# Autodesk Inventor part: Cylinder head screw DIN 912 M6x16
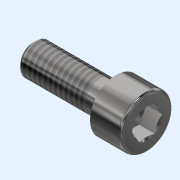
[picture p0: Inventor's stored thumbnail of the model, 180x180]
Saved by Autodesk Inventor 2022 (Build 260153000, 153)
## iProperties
Part Number: Cylinder head screw DIN 912 M6x16
Material: Generico
Catalog Web Link: www.cadenas.de
Description: DIN 912-Cylinder head screws cap screws
Vendor: METALWORK
Document SubType Name: Modeling
Designer: partserver
Manufacturer: METALWORK
Mass: 0.844568 g
Surface Area: 6.8049 cm^2
Volume: 0.844568 cm^3
Density: 1 g/cm^3
Appearance: Acciaio - Lucido
Category: PARTsolutions
Company: METALWORK
PSOL_IDENT_0: {$CADENAS_DATA\23d-libs\metalwork\commonpool\din_912.prj},208 {VTYP=3D},{NB=Cylinder head screw DIN
PSOL_IDENT_1: 912 M6x16},{LINA=Cylinder head screw DIN 912 M6x16},{NN=DIN 912},{DATE=09.11.2020 15:05:54},{GEOMDAT
PSOL_IDENT_2: E=27.11.2019 13:03:54},{VERSION=},{LINEID=690},{WBVAR=},{WBNUMERIC=}  {NB=Zylinderschraube DIN 912 M
PSOL_IDENT_3: 6x16},{LINA=Zylinderschraube DIN 912 M6x16},{KT=X},{IDNR=},{VER=x},{GEW=0},{D=6.000},{D3=4.773},{P=1
PSOL_IDENT_4: .000},{L=16.000},{B=13},{BX=24.000},{LS=0},{LG=3},{DK=10.000},{DA=6.800},{DS=6.000},{E=5.720},{F=0.6
PSOL_IDENT_5: 80},{K=6.000},{R=0.250},{S=5.000},{T=3.000},{V=0.600},{DW=9.380},{W=2.300},{NENN=M6x16}
NB: Cylinder head screw DIN 912 M6x16
NN: DIN 912
NT: Cylinder head screws cap screws
NBSYN: Cylinder head screw DIN 912 $NENN.
LINA: Cylinder head screw DIN 912 M6x16
CATALOG: Metalwork
VER: x
GEW: 0
D: 6
D3: 4.773
P: 1
L: 16
BX: 24
DK: 10
DA: 6.8
DS: 6
E: 5.72
F: 0.68
K: 6
R: 0.25
S: 5
T: 3
V: 0.6
DW: 9.38
W: 2.3
SUPPLIER: METALWORK
ARTICLENO: Cylinder head screw DIN 912 M6x16
BOMINFO: Cylinder head screw DIN 912 M6x16
CREATOR: CADENAS GmbH
Title: Cylinder head screw DIN 912 M6x16
Author: Cadenas PARTsolutions
Comments: Cylinder head screws cap screws
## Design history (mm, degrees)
sketch "Sketch_1"
  geometry: L1 (-16, 0)-(6, 0); L2 (3, 0)-(3, -2.5); L3 (3, -2.5)-(5.759, -2.5); L4 (5.759, -2.5)-(6, -2.917); L5 (6, -2.917)-(6, -4.4); L6 (5.4, -5)-(0, -5); L7 (0, -5)-(0, -3.4); L8 (-0.168, -3.164)-(-0.598, -3.014); L9 (-0.68, -3)-(-15.387, -3); L10 (-15.387, -3)-(-16, -2.386); L11 (-16, -2.386)-(-16, 0); L12 (-16, 0)-(3, 0); A1 r 0.6 centre (5.4, -4.4) between (5.4, -5) and (6, -4.4); A2 r 0.25 centre (-0.25, -3.4) between (0, -3.4) and (-0.168, -3.164); A3 r 0.25 centre (-0.68, -3.25) between (-0.598, -3.014) and (-0.68, -3)
  constraints: 24 end point, 6 point on circle, 3 centre point
revolve "Revolution1" sketch "Sketch_1" stored, may be unused: angle "d0" = 360 deg
thread "Thread1" dims "d1" = 12.3865, "d2" = 0
sketch "Skizze_1"
  geometry: L1 (-2.5, -1.443)-(0, -2.887); L2 (0, -2.887)-(2.5, -1.443); L3 (2.5, -1.443)-(2.5, 1.443); L4 (2.5, 1.443)-(0, 2.887); L5 (0, 2.887)-(-2.5, 1.443); L6 (-2.5, 1.443)-(-2.5, -1.443)
  constraints: 12 end point
extrude "Extrusion1" cut sketch "Skizze_1" distance "d3" = 3; taper "d4" = 0 deg
sketch "Sketch_4"
  geometry: L1 (-1.557, 0)-(-3, 0); L2 (-3, 0)-(-3, 2.5); L3 (-3, 2.5)-(-1.557, 0); L4 (-1.557, 0)-(-3, 0)
  constraints: 8 end point
revolve "Revolution2" sketch "Sketch_4" stored, may be unused: angle "d5" = 360 deg
node "ip1_XY"
node "ip1_YZ"
node "ip1_ZX"
node "ip1_X"
node "ip1_Y"
node "ip1_Z"
node "ip1_Center"
node "ip2_XY"
node "ip2_YZ"
node "ip2_ZX"
node "ip2_X"
node "ip2_Y"
node "ip2_Z"
node "ip2_Center"
node "ip3_XY"
node "ip3_YZ"
node "ip3_ZX"
node "ip3_X"
node "ip3_Y"
node "ip3_Z"
node "ip3_Center"
body "Solid1"
other parameters: "d6" = 0, "d7" = 0, "d8" = 0
